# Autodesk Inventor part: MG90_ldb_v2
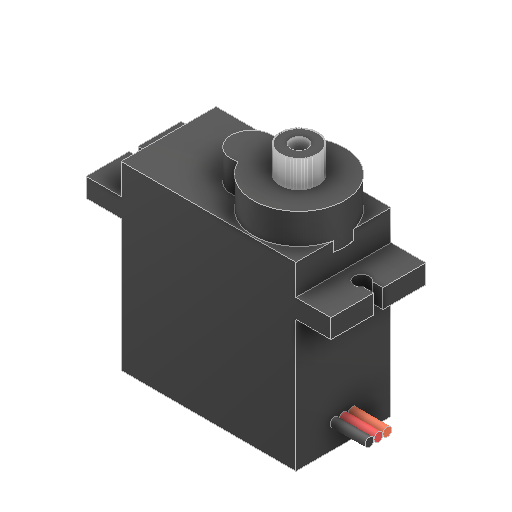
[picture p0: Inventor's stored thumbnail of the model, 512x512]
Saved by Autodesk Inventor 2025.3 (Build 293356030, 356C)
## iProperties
Created: 2019-07
Part Number: MG90_ldb_v2
Material: Steel
Document SubType Name: Modeling
Designer: Ryzen5700u
Density: 7.85 g/cm^3
Appearance: Default
Author: Ryzen5700u
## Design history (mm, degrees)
node "Geometria corretta1"
  node "Schizzo8-Invisible"
node "Solido1"
sketch "Schizzo2-Invisible"
sketch "Schizzo9-Invisible"
node "Schizzo11-Invisible"
node "Schizzo12-Invisible"
node "Schizzo6-Invisible"
sketch "Schizzo10-Invisible"
node "Schizzo7-Invisible"
node "Schizzo13-Invisible"
sketch "Schizzo1"
  geometry: L1 (23, -4.915)-(23, 0) reference; L2 (23, 0)-(0, 0) reference; L3 (0, 0)-(0, -12.5) reference; L4 (0, -12.5)-(23, -12.5) reference; L5 (23, -12.5)-(23, -7.585) reference; A1 r 6 centre (17.15, -6.25) between (23, -4.915) and (11.734, -3.666) reference; A2 r 6 centre (17.15, -6.25) between (11.734, -8.834) and (23, -7.585) reference; A3 r 2.7 centre (10.95, -6.25) between (11.734, -3.666) and (11.734, -8.834) reference; 1 further point
extrude "Estrusione1" join sketch "Schizzo1" distance "d0" = 1.3; taper "d1" = 0 deg
sketch "Schizzo2"
  geometry: L1 (4.6, 0)-(4.6, -12.5) reference; L2 (4.6, 0)-(0, 0) reference; L3 (0, 0)-(0, -5.65) reference; L4 (1.4, -5.65)-(0, -5.65) reference; L5 (1.4, -6.85)-(0, -6.85) reference; L6 (0, -6.85)-(0, -12.5) reference; L7 (4.6, -12.5)-(0, -12.5) reference; L8 (27.6, -12.5)-(27.6, 0) reference; L9 (27.6, -12.5)-(32.2, -12.5) reference; L10 (32.2, -12.5)-(32.2, -6.85) reference; L11 (30.8, -6.85)-(32.2, -6.85) reference; L12 (30.8, -5.65)-(32.2, -5.65) reference; L13 (32.2, -5.65)-(32.2, 0) reference; L14 (27.6, 0)-(32.2, 0) reference; A1 r 1 centre (2.2, -6.25) between (1.4, -6.85) and (1.4, -5.65) reference; A2 r 1 centre (30, -6.25) between (30.8, -5.65) and (30.8, -6.85) reference; 1 further point
extrude "Estrusione2" cut sketch "Schizzo2" distance "d5" = 1.7; taper "d6" = 0 deg
sketch "Schizzo3"
  geometry: L1 (4.6, 0)-(4.6, -12.5) reference; L2 (4.6, 0)-(0, 0) reference; L3 (0, 0)-(0, -5.65) reference; L4 (0, -5.65)-(1.4, -5.65) reference; L5 (1.4, -6.85)-(0, -6.85) reference; L6 (0, -6.85)-(0, -12.5) reference; L7 (4.6, -12.5)-(0, -12.5) reference; L8 (27.6, -12.5)-(27.6, 0) reference; L9 (27.6, -12.5)-(32.2, -12.5) reference; L10 (32.2, -12.5)-(32.2, -6.85) reference; L11 (32.2, -6.85)-(30.8, -6.85) reference; L12 (30.8, -5.65)-(32.2, -5.65) reference; L13 (32.2, -5.65)-(32.2, 0) reference; L14 (27.6, 0)-(32.2, 0) reference; A1 r 1 centre (2.2, -6.25) between (1.4, -6.85) and (1.4, -5.65) reference; A2 r 1 centre (30, -6.25) between (30.8, -5.65) and (30.8, -6.85) reference; 1 further point
extrude "Estrusione3" join sketch "Schizzo3" distance "d7" = 1.4; taper "d8" = 0 deg
sketch "Schizzo4"
  geometry: L1 (-0.548, -2.337)-(-0.45, -2.358) reference; L2 (-0.569, -2.434)-(-0.548, -2.337) reference; L3 (-0.694, -2.298)-(-0.725, -2.393) reference; L4 (-0.789, -2.267)-(-0.694, -2.298) reference; L5 (-0.82, -2.362)-(-0.789, -2.267) reference; L6 (-0.93, -2.213)-(-0.971, -2.304) reference; L7 (-1.022, -2.172)-(-0.93, -2.213) reference; L8 (-1.062, -2.263)-(-1.022, -2.172) reference; L9 (-1.157, -2.103)-(-1.206, -2.19) reference; L10 (-1.243, -2.053)-(-1.157, -2.103) reference; L11 (-1.293, -2.14)-(-1.243, -2.053) reference; L12 (-1.37, -1.971)-(-1.429, -2.052) reference; L13 (-1.451, -1.912)-(-1.37, -1.971) reference; L14 (-1.51, -1.993)-(-1.451, -1.912) reference; L15 (-1.569, -1.817)-(-1.635, -1.891) reference; L16 (-1.643, -1.75)-(-1.569, -1.817) reference; L17 (-1.71, -1.824)-(-1.643, -1.75) reference; L18 (-1.75, -1.643)-(-1.824, -1.71) reference; L19 (-1.817, -1.569)-(-1.75, -1.643) reference; L20 (-1.891, -1.635)-(-1.817, -1.569) reference; L21 (-1.912, -1.451)-(-1.993, -1.51) reference; L22 (-1.971, -1.37)-(-1.912, -1.451) reference; L23 (-2.052, -1.429)-(-1.971, -1.37) reference; L24 (-2.053, -1.243)-(-2.14, -1.293) reference; L25 (-2.103, -1.157)-(-2.053, -1.243) reference; L26 (-2.19, -1.206)-(-2.103, -1.157) reference; L27 (-2.172, -1.022)-(-2.263, -1.062) reference; L28 (-2.213, -0.93)-(-2.172, -1.022) reference; L29 (-2.304, -0.971)-(-2.213, -0.93) reference; L30 (-2.267, -0.789)-(-2.362, -0.82) reference; L31 (-2.298, -0.694)-(-2.267, -0.789) reference; L32 (-2.393, -0.725)-(-2.298, -0.694) reference; L33 (-2.337, -0.548)-(-2.434, -0.569) reference; L34 (-2.358, -0.45)-(-2.337, -0.548) reference; L35 (-2.455, -0.471)-(-2.358, -0.45) reference; L36 (-2.382, -0.301)-(-2.481, -0.311) reference; L37 (-2.392, -0.201)-(-2.382, -0.301) reference; L38 (-2.491, -0.212)-(-2.392, -0.201) reference; L39 (-2.4, -0.05)-(-2.499, -0.05) reference; L40 (-2.4, 0.05)-(-2.4, -0.05) reference; L41 (-2.499, 0.05)-(-2.4, 0.05) reference; L42 (-2.392, 0.201)-(-2.491, 0.212) reference; L43 (-2.382, 0.301)-(-2.392, 0.201) reference; L44 (-2.481, 0.311)-(-2.382, 0.301) reference; L45 (-2.358, 0.45)-(-2.455, 0.471) reference; L46 (-2.337, 0.548)-(-2.358, 0.45) reference; L47 (-2.434, 0.569)-(-2.337, 0.548) reference; L48 (-2.298, 0.694)-(-2.393, 0.725) reference; L49 (-2.267, 0.789)-(-2.298, 0.694) reference; L50 (-2.362, 0.82)-(-2.267, 0.789) reference; L51 (-2.213, 0.93)-(-2.304, 0.971) reference; L52 (-2.172, 1.022)-(-2.213, 0.93) reference; L53 (-2.263, 1.062)-(-2.172, 1.022) reference; L54 (-2.103, 1.157)-(-2.19, 1.206) reference; L55 (-2.053, 1.243)-(-2.103, 1.157) reference; L56 (-2.14, 1.293)-(-2.053, 1.243) reference; L57 (-1.971, 1.37)-(-2.052, 1.429) reference; L58 (-1.912, 1.451)-(-1.971, 1.37) reference; L59 (-1.993, 1.51)-(-1.912, 1.451) reference; L60 (-1.817, 1.569)-(-1.891, 1.635) reference; L61 (-1.75, 1.643)-(-1.817, 1.569) reference; L62 (-1.824, 1.71)-(-1.75, 1.643) reference; L63 (-1.643, 1.75)-(-1.71, 1.824) reference; L64 (-1.569, 1.817)-(-1.643, 1.75) reference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; A1 r 6 centre (0, 0) between (-5.416, -2.584) and (-5.416, 2.584) reference; A2 r 2.7 centre (-6.2, 0) between (-5.416, 2.584) and (-5.416, -2.584) reference; A3 r 2.5 centre (0, 0) between (-0.725, -2.393) and (-0.569, -2.434) reference; A4 r 2.5 centre (0, 0) between (-0.971, -2.304) and (-0.82, -2.362) reference; A5 r 2.5 centre (0, 0) between (-1.206, -2.19) and (-1.062, -2.263) reference; A6 r 2.5 centre (0, 0) between (-1.429, -2.052) and (-1.293, -2.14) reference; A7 r 2.5 centre (0, 0) between (-1.635, -1.891) and (-1.51, -1.993) reference; A8 r 2.5 centre (0, 0) between (-1.824, -1.71) and (-1.71, -1.824) reference; A9 r 2.5 centre (0, 0) between (-1.993, -1.51) and (-1.891, -1.635) reference; A10 r 2.5 centre (0, 0) between (-2.14, -1.293) and (-2.052, -1.429) reference; A11 r 2.5 centre (0, 0) between (-2.263, -1.062) and (-2.19, -1.206) reference; A12 r 2.5 centre (0, 0) between (-2.362, -0.82) and (-2.304, -0.971) reference; A13 r 2.5 centre (0, 0) between (-2.434, -0.569) and (-2.393, -0.725) reference; A14 r 2.5 centre (0, 0) between (-2.481, -0.311) and (-2.455, -0.471) reference; A15 r 2.5 centre (0, 0) between (-2.499, -0.05) and (-2.491, -0.212) reference; A16 r 2.5 centre (0, 0) between (-2.491, 0.212) and (-2.499, 0.05) reference; A17 r 2.5 centre (0, 0) between (-2.455, 0.471) and (-2.481, 0.311) reference; A18 r 2.5 centre (0, 0) between (-2.393, 0.725) and (-2.434, 0.569) reference; A19 r 2.5 centre (0, 0) between (-2.304, 0.971) and (-2.362, 0.82) reference; A20 r 2.5 centre (0, 0) between (-2.19, 1.206) and (-2.263, 1.062) reference; A21 r 2.5 centre (0, 0) between (-2.052, 1.429) and (-2.14, 1.293) reference; A22 r 2.5 centre (0, 0) between (-1.891, 1.635) and (-1.993, 1.51) reference; A23 r 2.5 centre (0, 0) between (-1.71, 1.824) and (-1.824, 1.71) reference; A24 r 2.5 centre (0, 0) between (-1.51, 1.993) and (-1.635, 1.891) reference; A25 r 2.5 centre (0, 0) between (-1.293, 2.14) and (-1.429, 2.052) reference; A26 r 2.5 centre (0, 0) between (-1.062, 2.263) and (-1.206, 2.19) reference; A27 r 2.5 centre (0, 0) between (-0.82, 2.362) and (-0.971, 2.304) reference; A28 r 2.5 centre (0, 0) between (-0.569, 2.434) and (-0.725, 2.393) reference; A29 r 2.5 centre (0, 0) between (-0.311, 2.481) and (-0.471, 2.455) reference; A30 r 2.5 centre (0, 0) between (-0.05, 2.499) and (-0.212, 2.491) reference; A31 r 2.5 centre (0, 0) between (0.212, 2.491) and (0.05, 2.499) reference; A32 r 2.5 centre (0, 0) between (0.471, 2.455) and (0.311, 2.481) reference; A33 r 2.5 centre (0, 0) between (0.725, 2.393) and (0.569, 2.434) reference; A34 r 2.5 centre (0, 0) between (0.971, 2.304) and (0.82, 2.362) reference; A35 r 2.5 centre (0, 0) between (1.206, 2.19) and (1.062, 2.263) reference; A36 r 2.5 centre (0, 0) between (1.429, 2.052) and (1.293, 2.14) reference; A37 r 2.5 centre (0, 0) between (1.635, 1.891) and (1.51, 1.993) reference; A38 r 2.5 centre (0, 0) between (1.824, 1.71) and (1.71, 1.824) reference; A39 r 2.5 centre (0, 0) between (1.993, 1.51) and (1.891, 1.635) reference; A40 r 2.5 centre (0, 0) between (2.14, 1.293) and (2.052, 1.429) reference; A41 r 2.5 centre (0, 0) between (2.263, 1.062) and (2.19, 1.206) reference; A42 r 2.5 centre (0, 0) between (2.362, 0.82) and (2.304, 0.971) reference; A43 r 2.5 centre (0, 0) between (2.434, 0.569) and (2.393, 0.725) reference; A44 r 2.5 centre (0, 0) between (2.481, 0.311) and (2.455, 0.471) reference; A45 r 2.5 centre (0, 0) between (2.499, 0.05) and (2.491, 0.212) reference; A46 r 2.5 centre (0, 0) between (2.491, -0.212) and (2.499, -0.05) reference; A47 r 2.5 centre (0, 0) between (2.455, -0.471) and (2.481, -0.311) reference; A48 r 2.5 centre (0, 0) between (2.393, -0.725) and (2.434, -0.569) reference; A49 r 2.5 centre (0, 0) between (2.304, -0.971) and (2.362, -0.82) reference; A50 r 2.5 centre (0, 0) between (2.19, -1.206) and (2.263, -1.062) reference; A51 r 2.5 centre (0, 0) between (2.052, -1.429) and (2.14, -1.293) reference; A52 r 2.5 centre (0, 0) between (1.891, -1.635) and (1.993, -1.51) reference; A53 r 2.5 centre (0, 0) between (1.71, -1.824) and (1.824, -1.71) reference; A54 r 2.5 centre (0, 0) between (1.51, -1.993) and (1.635, -1.891) reference; A55 r 2.5 centre (0, 0) between (1.293, -2.14) and (1.429, -2.052) reference; A56 r 2.5 centre (0, 0) between (1.062, -2.263) and (1.206, -2.19) reference; A57 r 2.5 centre (0, 0) between (0.82, -2.362) and (0.971, -2.304) reference; A58 r 2.5 centre (0, 0) between (0.569, -2.434) and (0.725, -2.393) reference; A59 r 2.5 centre (0, 0) between (0.311, -2.481) and (0.471, -2.455) reference; A60 r 2.5 centre (0, 0) between (0.05, -2.499) and (0.212, -2.491) reference; A61 r 2.5 centre (0, 0) between (-0.212, -2.491) and (-0.05, -2.499) reference; A62 r 2.5 centre (0, 0) between (-0.471, -2.455) and (-0.311, -2.481) reference; 1 further point
extrude "Estrusione4" cut sketch "Schizzo4" distance "d9" = 0.7; taper "d10" = 0 deg
sketch "Schizzo5"
  geometry: C1 r 1.1 at (0, 0) reference; C2 r 3.334 at (0, 0); 1 further point
  constraints: 1 centre point, 1 coincident
extrude "Estrusione5" cut sketch "Schizzo5" distance "d11" = 1.2; taper "d12" = 0 deg
node "Modifica diretta1"
node "Modifica diretta2"
node "Solido2"
node "Linea chiusa proiettata1"
node "Linea chiusa proiettata2"
node "Linea chiusa proiettata3"
node "Linea chiusa proiettata4"
node "Linea chiusa proiettata5"
node "Linea chiusa proiettata6"
feature "Sposta1" dims "d13" = -1.5
feature "Sposta2" dims "d16" = -1.5
other parameters: "d14" = 0, "d15" = 0, "d17" = 0, "d18" = 0
